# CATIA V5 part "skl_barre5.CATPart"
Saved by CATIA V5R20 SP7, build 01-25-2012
Part number: skl_barre5
Publications: "axe_pivot_5_4", "axe_pivot_5_0", "PointG", "PointF", "PlanRef"
Bounding box of the stored display mesh (mm): x 0 to 20, y -214 to 85.111, z 106.172 to 129.244
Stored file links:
  U:\Projet IAO\omeyer\Catia\skl_barre5.CATPart
  U:\Projet IAO\omeyer\Catia\skl_748.CATProduct
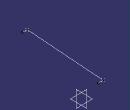
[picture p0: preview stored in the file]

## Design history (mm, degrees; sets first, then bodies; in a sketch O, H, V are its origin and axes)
Set1
  DatumPoint1 "PointG": linked copy from another document
  DatumPoint2 "PointF": linked copy from another document
  Plane1 "PlanRef": linked copy from another document
Set2
  Line1: type PtPt, FirstPoint DatumPoint1, SecondPoint DatumPoint2
  Line2 "axe_pivot_5_0": type Normal, RefPoint DatumPoint1, RefSkin Plane1, Start 0, End 20
  Line3 "axe_pivot_5_4": type Normal, RefPoint DatumPoint2, RefSkin Plane1, Start 0, End 20
Body1 (main body)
